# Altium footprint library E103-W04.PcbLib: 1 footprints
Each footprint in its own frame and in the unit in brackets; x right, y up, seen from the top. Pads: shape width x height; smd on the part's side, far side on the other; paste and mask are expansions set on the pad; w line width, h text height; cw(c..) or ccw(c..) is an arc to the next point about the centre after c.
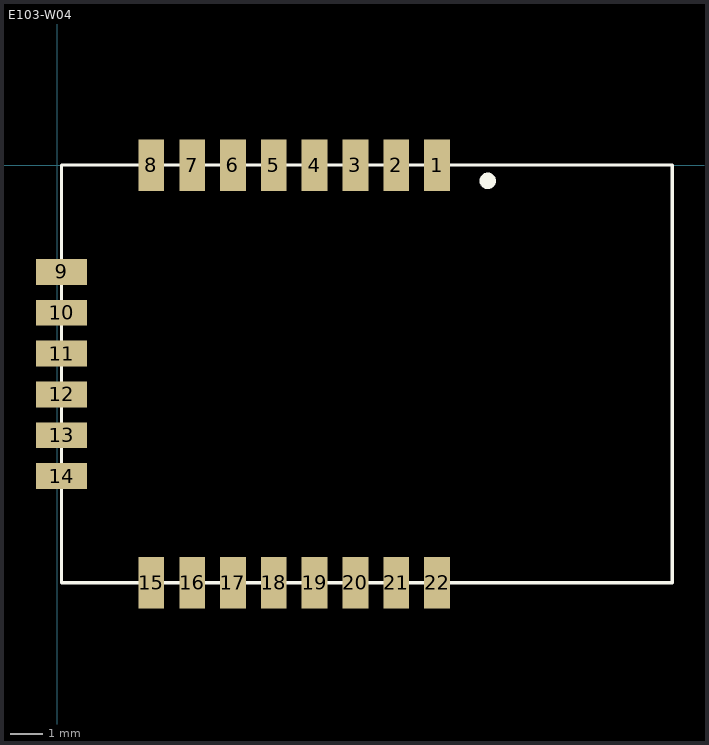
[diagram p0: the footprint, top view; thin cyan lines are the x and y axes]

## E103-W04 [mm]
pads (22):
  rect 0.8x1.6 smd: 1(11.811,0) 2(10.541,0) 3(9.271,0) 4(8.001,0) 5(6.731,0) 6(5.461,0) 7(4.191,0) 8(2.921,0) 15(2.921,-13) 16(4.191,-13) 17(5.461,-13) 18(6.731,-13) 19(8.001,-13) 20(9.271,-13) 21(10.541,-13) 22(11.811,-13)
  rect 1.6x0.8 smd: 9(0.127,-3.325) 10(0.127,-4.595) 11(0.127,-5.865) 12(0.127,-7.135) 13(0.127,-8.405) 14(0.127,-9.675)
Top Overlay:
  circle w0.2: c13.387,-0.49 r0.155
  circle w0.2: c13.377,-0.49 r0.045
  lines w0.1: 0.127,-12.994 0.127,-12.75 0.127,0 19.127,0 19.127,-12.998 0.131,-12.998 0.127,-12.994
